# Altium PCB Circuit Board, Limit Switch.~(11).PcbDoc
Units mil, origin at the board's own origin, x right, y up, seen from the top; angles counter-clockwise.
Board outline 1122.99 x 1124 mil, 2 copper layers (Top Layer, Bottom Layer); 0 components, 2 nets, 8 pads, 0 vias.
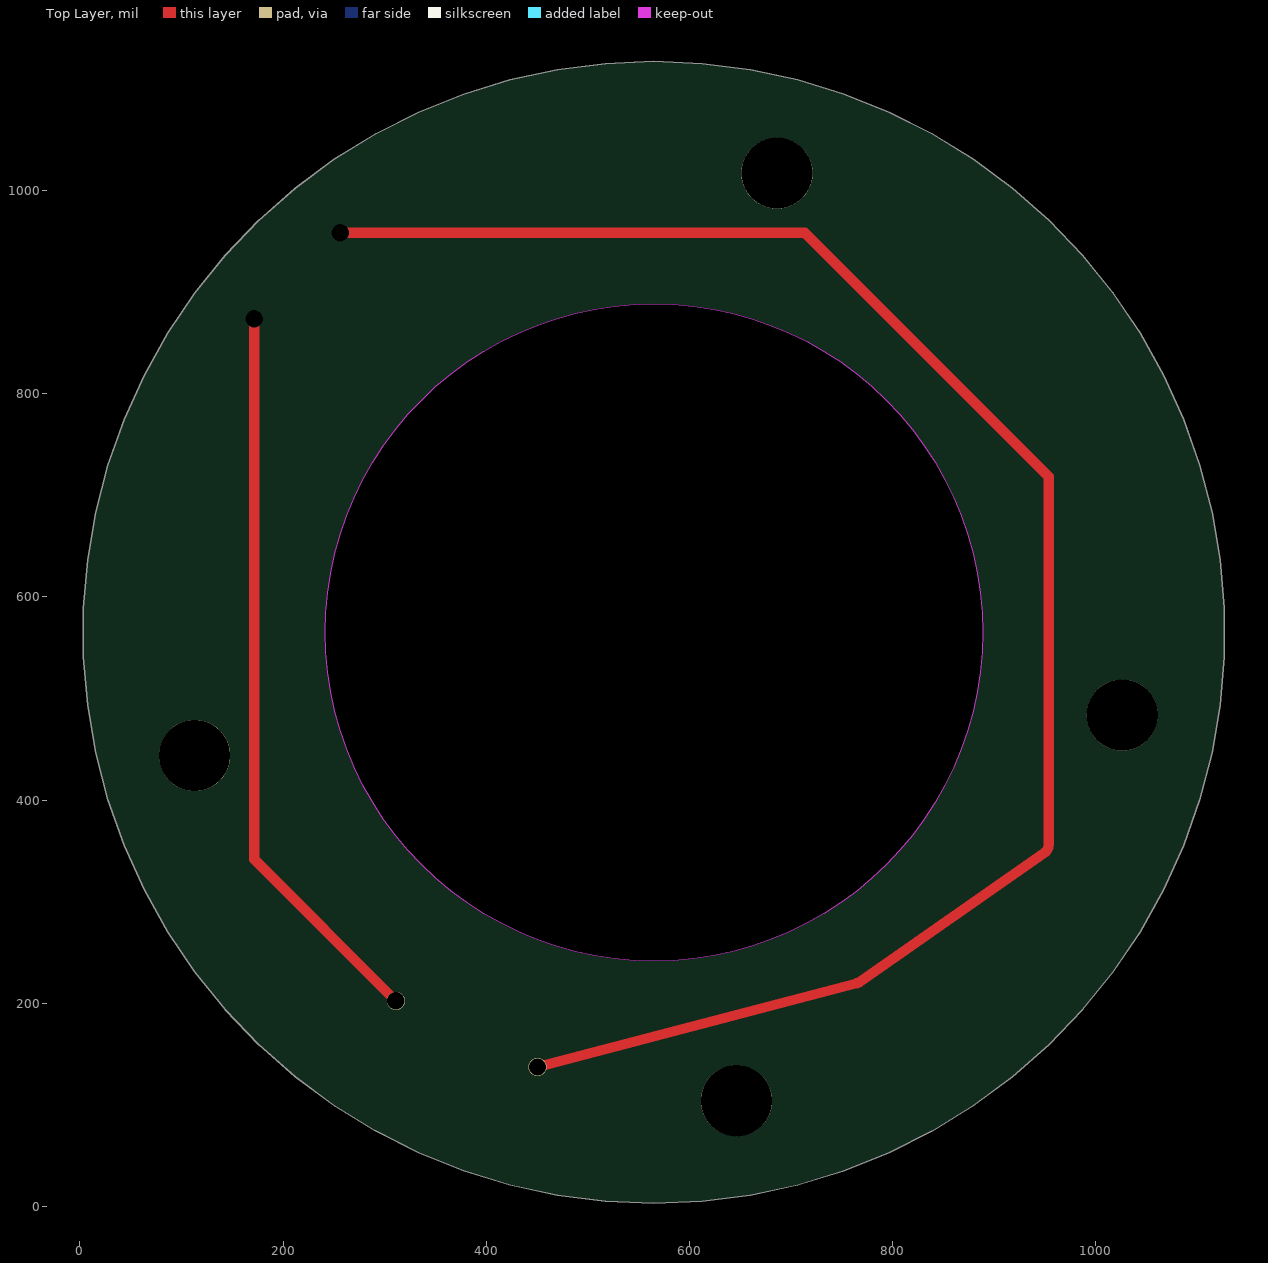
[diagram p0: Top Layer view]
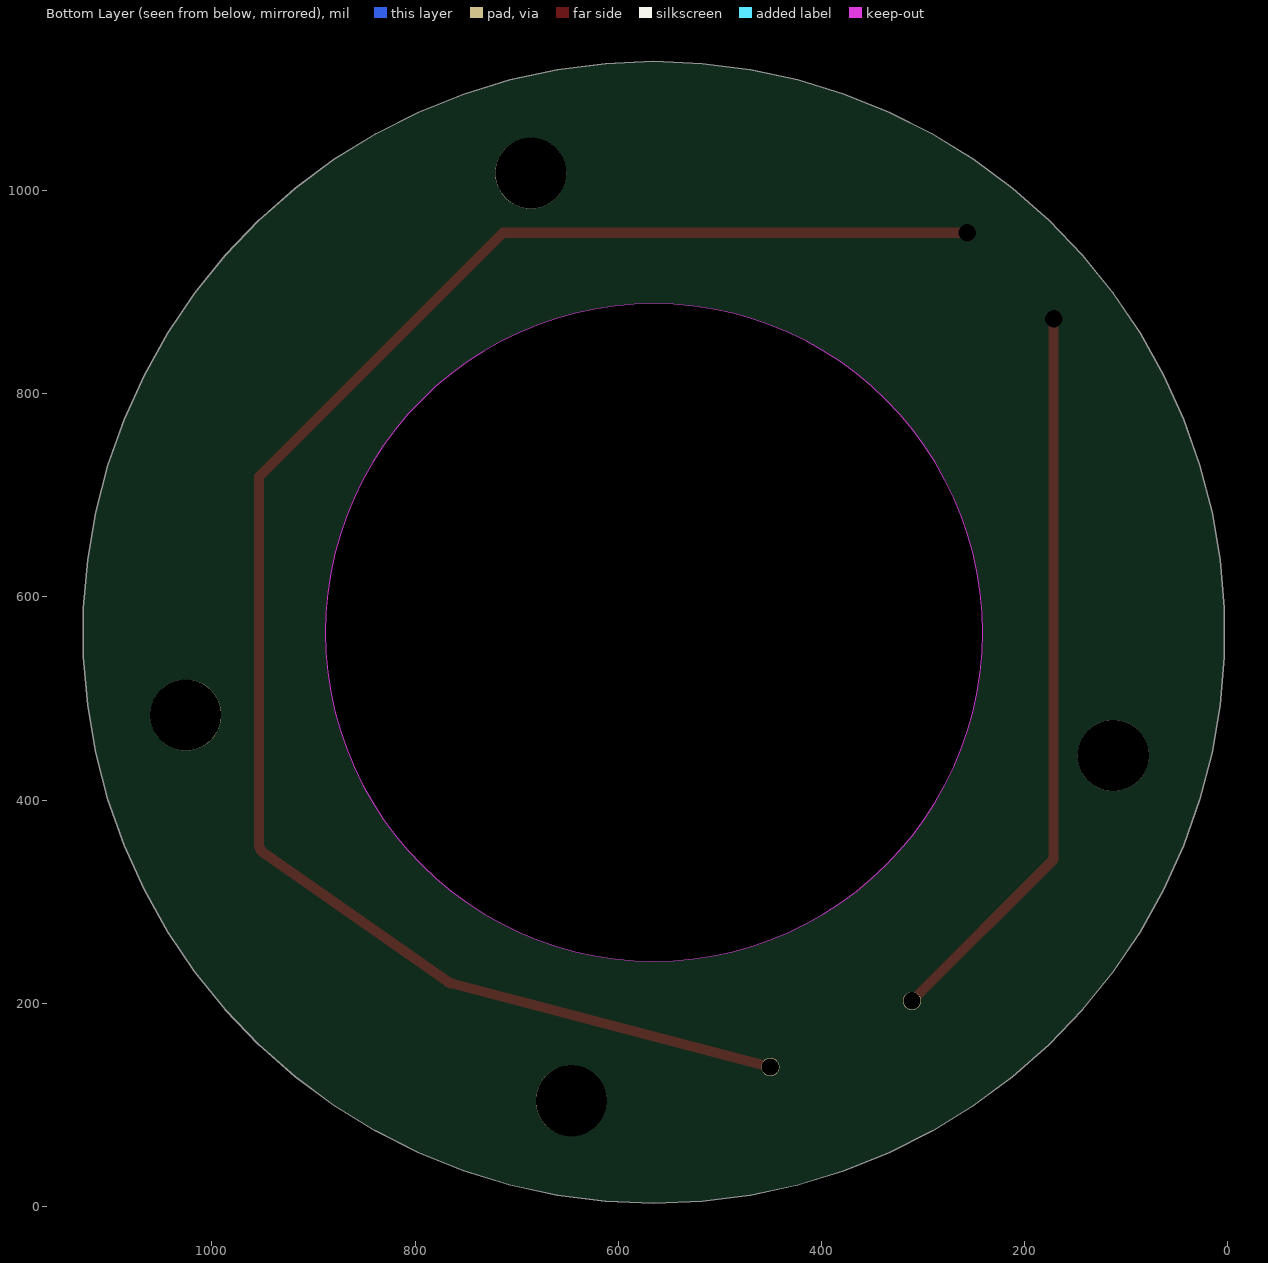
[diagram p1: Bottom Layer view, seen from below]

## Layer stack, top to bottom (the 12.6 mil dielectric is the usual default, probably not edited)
Top Solder: solder mask 0.4, Solder Resist, Dk 3.5
Top Layer: signal copper 1.4
Dielectric1: dielectric 12.6, FR-4, Dk 4.8
Bottom Layer: signal copper 1.4
Bottom Solder: solder mask 0.4, Solder Resist, Dk 3.5

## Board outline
565,1127 517.34,1124.98 470.02,1118.92 423.39,1108.87 377.78,1094.9 333.51,1077.11 290.92,1055.63 250.29,1030.62 211.94,1002.26 176.13,970.74 143.12,936.3 113.15,899.18 86.44,859.66 63.18,818.01 43.53,774.55 27.63,729.57 15.61,683.4 7.55,636.38 3.51,588.85 3.51,541.15 7.55,493.62 15.61,446.6 27.63,400.43 43.53,355.45 63.18,311.99 86.44,270.34 113.15,230.82 143.12,193.7 176.13,159.26 211.94,127.74 250.29,99.38 290.92,74.37 333.51,52.89 377.78,35.1 423.39,21.13 470.02,11.08 517.34,5.02 565,3 612.66,5.02 659.98,11.08 706.61,21.13 752.22,35.1 796.49,52.89 839.08,74.37 879.71,99.38 918.06,127.74 953.87,159.26 986.88,193.7 1016.85,230.82 1043.56,270.34 1066.82,311.99 1086.47,355.45 1102.37,400.43 1114.39,446.6 1122.45,493.62 1126.49,541.15 1126.49,588.85 1122.45,636.38 1114.39,683.4 1102.37,729.57 1086.47,774.55 1066.82,818.01 1043.56,859.66 1016.85,899.18 986.88,936.3 953.87,970.74 918.06,1002.26 879.71,1030.62 839.08,1055.63 796.49,1077.11 752.22,1094.9 706.61,1108.87 659.98,1118.92 612.66,1124.98
cut-out: 565,241.5 cw(c565,565) 241.5,565 cw(c565,565) 565,888.5 cw(c565,565) 888.5,565 cw(c565,565)

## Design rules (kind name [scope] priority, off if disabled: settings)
Clearance [All] p1: gap=10 ignorepadtopadclearanceinfootprint=FALSE except(0: Arc-Hole Track-Hole SMDPad-Hole THPad-Hole Via-Hole Fill-Hole Poly-Hole Region-Hole Text-Hole)
PolygonConnect [All] p1: connectstyle=Relief reliefconductorwidth=10 reliefentries=4 polygonreliefangle="90 Angle" airgapwidth=10
RoutingVias [All] p1: holewidth=28 width=50 viastyle="Through Hole" minholewidth=28 minwidth=50 maxholewidth=28 maxwidth=50
SilkToSolderMaskClearance SilkscreenOverComponentPads [IsPad] p1: minsilkscreentomaskgap=10 clearancetoexposedcopper=TRUE
SolderMaskExpansion [All] p1: expansion=4 istentingtop=FALSE
Width [All] p1: maxlimit=10 minlimit=10 preferedwidth=10
29 further rules are at their usual default settings.

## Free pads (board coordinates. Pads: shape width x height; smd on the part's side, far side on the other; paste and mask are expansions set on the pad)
  round 70 hole 70 unplated: 1(112.95,443.87)
  round 16.1 hole 17.1: 1(171.57,873.57) 1(256.43,958.42)
  round 18 hole 17.1: 1(311.05,202.32) 1(450.41,137.34)
  round 70 hole 70: 1(646.27,104.11) 1(686.13,1017.05) 1(1025.89,483.73)

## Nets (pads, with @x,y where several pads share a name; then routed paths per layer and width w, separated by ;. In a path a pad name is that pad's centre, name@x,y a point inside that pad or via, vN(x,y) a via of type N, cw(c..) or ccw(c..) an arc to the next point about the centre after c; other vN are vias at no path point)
SW1: pad.1@171.57,873.57 pad.1@311.05,202.32 | length 729
  Top Layer w10: pad.1@171.57,873.57 171.57,341.79 pad.1@311.05,202.32
SW2: pad.1@256.43,958.42 pad.1@450.41,137.34 | length 1718.1
  Top Layer w10: pad.1@256.43,958.42 713.49,958.42 953.65,718.27 953.65,356.4 cw(c943.65,356.4) 949.36,348.19 767.91,221.17 cw(c762.17,229.36) 764.68,219.69 pad.1@450.41,137.34

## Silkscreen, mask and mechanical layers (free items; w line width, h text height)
Mechanical 1:
  circle w10: c565,565 r323.5
  circle w10: c565,565 r562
